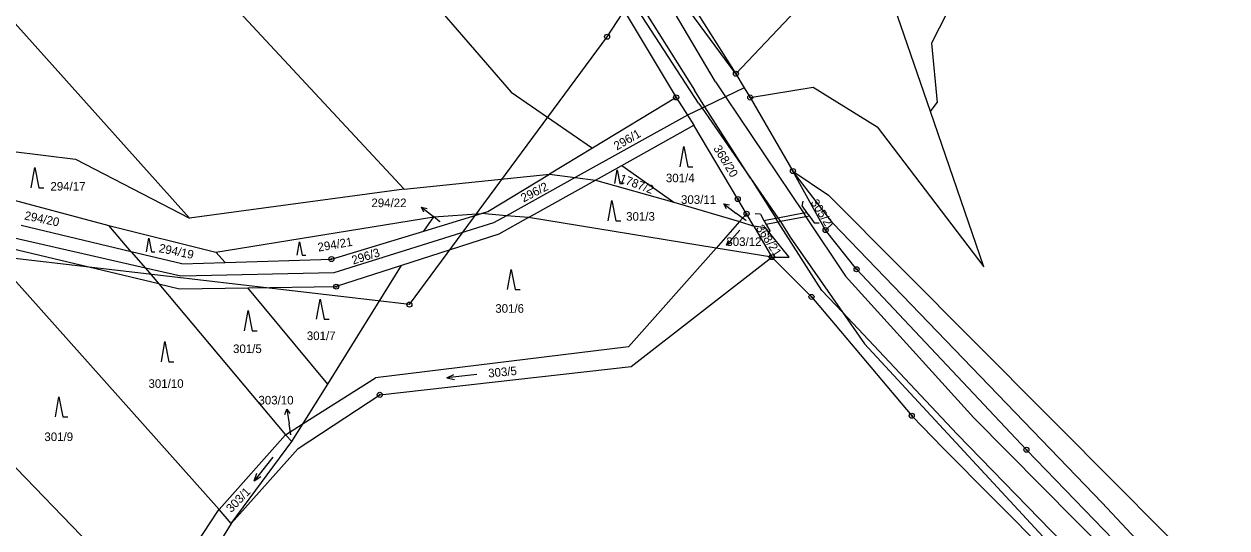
# Model space of a CAD drawing. Extents: x -762263 to -760336, y -1154405 to -1152076.
# Drawn here: x -761124.8 to -760886.7, y -1153787.3 to -1153687.5 of the extents above; entities that cross this region are included whole.
import ezdxf

# ---------------------------------------------------------------- set-up
doc = ezdxf.new("R2010")
doc.units = 0
for name, color, linetype in [('Vrstva 1', 7, 'Continuous'), ('Vrstva 10', 7, 'Continuous'), ('Vrstva 12', 7, 'Continuous'), ('Vrstva 13', 7, 'Continuous'), ('Vrstva 16', 7, 'Continuous'), ('Vrstva 18', 7, 'Continuous'), ('Vrstva 24', 7, 'Continuous'), ('Vrstva 25', 7, 'Continuous'), ('Vrstva 26', 7, 'Continuous'), ('Vrstva 4', 7, 'Continuous'), ('Vrstva 6', 7, 'Continuous')]:
    doc.layers.add(name, color=color, linetype=linetype)

msp = doc.modelspace()

# ---------------------------------------------------------------- linework, layer by layer
at = {"layer": 'Vrstva 1'}
for p, q in [((-760991.27, -1153703.15), (-761052.6, -1153608.54)), ((-760928.42, -1153658.17), (-760945.15, -1153691.28)), ((-760983.9, -1153697.32), (-760959.99, -1153671.97)), ((-760983.9, -1153697.32), (-761000.86, -1153674.38)), ((-761008.97, -1153679.88), (-760995.71, -1153702.01)), ((-760945.38, -1153704.81), (-760953.71, -1153680.58)), ((-760991.4, -1153685.47), (-760983.9, -1153697.32)), ((-760945.15, -1153691.28), (-760944.07, -1153703.02)), ((-760983.9, -1153697.32), (-760982.23, -1153700.09)), ((-760982.23, -1153700.09), (-760981.06, -1153702.03)), ((-760981.06, -1153702.03), (-760968.63, -1153699.98)), ((-760968.63, -1153699.98), (-760955.91, -1153707.82)), ((-760995.71, -1153702.01), (-761012.25, -1153712.06)), ((-760995.71, -1153702.01), (-760993.47, -1153705.56)), ((-760981.06, -1153702.03), (-760972.6, -1153716.6)), ((-760945.38, -1153704.81), (-760944.07, -1153703.02)), ((-760991.27, -1153703.15), (-760990.58, -1153704.16)), ((-760990.58, -1153704.16), (-760981.02, -1153718.01)), ((-760934.8, -1153735.55), (-760945.38, -1153704.81)), ((-761006.49, -1153715.49), (-760992.23, -1153707.52)), ((-760993.47, -1153705.56), (-760992.23, -1153707.52)), ((-760983.52, -1153722.14), (-760992.23, -1153707.52)), ((-760955.91, -1153707.82), (-760934.8, -1153735.55)), ((-761012.25, -1153712.06), (-761020.81, -1153717.25)), ((-761032.98, -1153724.64), (-761020.81, -1153717.25)), ((-761020.81, -1153717.25), (-761015.68, -1153717.89)), ((-761011.67, -1153718.39), (-761006.49, -1153715.49)), ((-760966.13, -1153728.28), (-760972.6, -1153716.6)), ((-760964.72, -1153726.91), (-760972.6, -1153716.6)), ((-760972.6, -1153716.6), (-760965.58, -1153721.41)), ((-761024.92, -1153725.81), (-761011.67, -1153718.39)), ((-761015.68, -1153717.89), (-761011.67, -1153718.39)), ((-760981.02, -1153718.01), (-760975.59, -1153725.89)), ((-760981.78, -1153725.05), (-760983.52, -1153722.14)), ((-760907.58, -1153779.67), (-760965.58, -1153721.41)), ((-761045.64, -1153728.48), (-761034.25, -1153725.02)), ((-761034.25, -1153725.02), (-761032.98, -1153724.64)), ((-761029.28, -1153725.44), (-761034.25, -1153725.02)), ((-761024.92, -1153725.81), (-761030.81, -1153729.1)), ((-761024.92, -1153725.81), (-761029.28, -1153725.44)), ((-760983.17, -1153726.62), (-760987.8, -1153731.85)), ((-760981.78, -1153725.05), (-760983.17, -1153726.62)), ((-760980.35, -1153727.51), (-760981.78, -1153725.05)), ((-760975.59, -1153725.89), (-760975.09, -1153726.62)), ((-760975.09, -1153726.62), (-760973.17, -1153729.68)), ((-760966.13, -1153728.28), (-760964.72, -1153726.91)), ((-760964.72, -1153726.91), (-760911.39, -1153782.31)), ((-761103.58, -1153732.57), (-761125.37, -1153727.38)), ((-761063.95, -1153734.04), (-761045.64, -1153728.48)), ((-761030.81, -1153729.1), (-761050.11, -1153735.34)), ((-760978.04, -1153727.86), (-760980.35, -1153727.51)), ((-760980.35, -1153727.51), (-760976.8, -1153733.64)), ((-760973.38, -1153733.63), (-760978.04, -1153727.86)), ((-760959.99, -1153736.06), (-760966.13, -1153728.28)), ((-760973.17, -1153729.68), (-760962.77, -1153744.57)), ((-761098.09, -1153738.93), (-761127.23, -1153731.99)), ((-761093.57, -1153734.96), (-761103.58, -1153732.57)), ((-761103.58, -1153732.57), (-761100.75, -1153735.85)), ((-761084.95, -1153734.69), (-761063.95, -1153734.04)), ((-760987.8, -1153731.85), (-761005.12, -1153751.4)), ((-760976.8, -1153733.64), (-760973.38, -1153733.63)), ((-761100.75, -1153735.85), (-761098.09, -1153738.93)), ((-761093.57, -1153734.96), (-761084.95, -1153734.69)), ((-761050.11, -1153735.34), (-761062.98, -1153739.5)), ((-760926.38, -1153771.8), (-760959.99, -1153736.06)), ((-761098.09, -1153738.93), (-761093.99, -1153739.91)), ((-761093.99, -1153739.91), (-761080.49, -1153739.73)), ((-761080.49, -1153739.73), (-761062.98, -1153739.5)), ((-760962.77, -1153744.57), (-760958.41, -1153750.81)), ((-761005.12, -1153751.4), (-761055.22, -1153757.55)), ((-760899.41, -1153814.59), (-760958.41, -1153750.81)), ((-761069.57, -1153766.63), (-761055.22, -1153757.55)), ((-761073.03, -1153768.82), (-761069.57, -1153766.63)), ((-761086.16, -1153783.65), (-761073.03, -1153768.82)), ((-760926.38, -1153771.8), (-760907.22, -1153791.59)), ((-760907.58, -1153779.67), (-760886.7, -1153800.7)), ((-761099.25, -1153803.44), (-761086.46, -1153783.99)), ((-761086.46, -1153783.99), (-761086.16, -1153783.65)), ((-760911.39, -1153782.31), (-760891.66, -1153803.33))]:
    msp.add_line(p, q, dxfattribs=at)
at = {"layer": 'Vrstva 10'}
for p, q in [((-760982.23, -1153700.09), (-760985.94, -1153701.89)), ((-760985.94, -1153701.89), (-760990.01, -1153703.87)), ((-760990.58, -1153704.16), (-760993.47, -1153705.56)), ((-760990.01, -1153703.87), (-760990.58, -1153704.16)), ((-760993.47, -1153705.56), (-761015.68, -1153717.89)), ((-761015.68, -1153717.89), (-761029.28, -1153725.44)), ((-761031.89, -1153726.89), (-761063.47, -1153736.75)), ((-761029.28, -1153725.44), (-761031.89, -1153726.89)), ((-761100.75, -1153735.85), (-761126.41, -1153729.97)), ((-761093.78, -1153737.45), (-761100.75, -1153735.85)), ((-761063.47, -1153736.75), (-761093.78, -1153737.45))]:
    msp.add_line(p, q, dxfattribs=at)
at = {"layer": 'Vrstva 12'}
for p, q in [((-761009.38, -1153690), (-760994.3, -1153666.9)), ((-761048.52, -1153743.06), (-761009.38, -1153690)), ((-761048.52, -1153743.06), (-761141.28, -1153732.19))]:
    msp.add_line(p, q, dxfattribs=at)
at = {"layer": 'Vrstva 13'}
for p, q in [((-761004.61, -1153755.29), (-760976.8, -1153733.64)), ((-760976.8, -1153733.64), (-760968.93, -1153741.52)), ((-760968.93, -1153741.52), (-760964.27, -1153747.04)), ((-760964.27, -1153747.04), (-760949.08, -1153765.07)), ((-761054.38, -1153760.92), (-761004.61, -1153755.29)), ((-761070.52, -1153771.55), (-761054.38, -1153760.92)), ((-760949.08, -1153765.07), (-760942.84, -1153771.46)), ((-761083.77, -1153786.39), (-761070.52, -1153771.55)), ((-760942.84, -1153771.46), (-760932.94, -1153781.45)), ((-760932.94, -1153781.45), (-760916.7, -1153797.84)), ((-761083.77, -1153786.39), (-761096.39, -1153806.55))]:
    msp.add_line(p, q, dxfattribs=at)
at = {"layer": 'Vrstva 16'}
for p, q in [((-761046.109, -1153723.751), (-761043.77, -1153725.63)), ((-760986.274, -1153723.102), (-760983.88, -1153724.91)), ((-761042.49, -1153726.66), (-761043.77, -1153725.63)), ((-760981.9, -1153726.4), (-760983.88, -1153724.91)), ((-761072.797, -1153763.735), (-761072.34, -1153766.7)), ((-761072.01, -1153768.85), (-761072.34, -1153766.7))]:
    msp.add_line(p, q, dxfattribs=at)
for points in [[(-761045.642, -1153724.767), (-761046.109, -1153723.751), (-761045.016, -1153723.988)], [(-760985.777, -1153724.104), (-760986.274, -1153723.102), (-760985.175, -1153723.306)], [(-761073.139, -1153764.8), (-761072.797, -1153763.735), (-761072.151, -1153764.647)]]:
    msp.add_lwpolyline(points, dxfattribs=at)
at = {"layer": 'Vrstva 24'}
for centre, radius in [((-760983.9, -1153697.32), 0.5), ((-760983.9, -1153697.32), 0.1), ((-760995.71, -1153702.01), 0.5), ((-760995.71, -1153702.01), 0.1), ((-760981.06, -1153702.03), 0.5), ((-760981.06, -1153702.03), 0.1), ((-760972.6, -1153716.6), 0.5), ((-760972.6, -1153716.6), 0.1), ((-760983.52, -1153722.14), 0.5), ((-760983.52, -1153722.14), 0.1), ((-760981.78, -1153725.05), 0.5), ((-760981.78, -1153725.05), 0.1), ((-760966.13, -1153728.28), 0.5), ((-760966.13, -1153728.28), 0.1), ((-761063.95, -1153734.04), 0.5), ((-761063.95, -1153734.04), 0.1), ((-760976.8, -1153733.64), 0.5), ((-760976.8, -1153733.64), 0.1), ((-760959.99, -1153736.06), 0.5), ((-760959.99, -1153736.06), 0.1), ((-761062.98, -1153739.5), 0.5), ((-761062.98, -1153739.5), 0.1), ((-760968.93, -1153741.52), 0.5), ((-760968.93, -1153741.52), 0.1), ((-761054.38, -1153760.92), 0.5), ((-761054.38, -1153760.92), 0.1), ((-760949.08, -1153765.07), 0.5), ((-760949.08, -1153765.07), 0.1), ((-760926.38, -1153771.8), 0.5), ((-760926.38, -1153771.8), 0.1)]:
    msp.add_circle(centre, radius, dxfattribs=at)
at = {"layer": 'Vrstva 25'}
for points in [[(-760994.91, -1153715.76), (-760994.21, -1153711.76), (-760993.41, -1153715.76), (-760992.41, -1153715.76)], [(-761123.38, -1153719.93), (-761122.68, -1153715.93), (-761121.88, -1153719.93), (-761120.88, -1153719.93)], [(-761007.859, -1153719.06), (-761007.39, -1153716.38), (-761006.854, -1153719.06), (-761006.184, -1153719.06)], [(-761009.17, -1153726.44), (-761008.47, -1153722.44), (-761007.67, -1153726.44), (-761006.67, -1153726.44)], [(-760983.084, -1153728.279), (-760985.756, -1153731.281), (-760984.838, -1153730.753)], [(-761100.559, -1153732.6), (-761100.09, -1153729.92), (-761099.554, -1153732.6), (-761098.884, -1153732.6)], [(-761070.719, -1153733.28), (-761070.25, -1153730.6), (-761069.714, -1153733.28), (-761069.044, -1153733.28)], [(-760985.756, -1153731.281), (-760985.338, -1153730.308)], [(-761029.1, -1153740.07), (-761028.4, -1153736.07), (-761027.6, -1153740.07), (-761026.6, -1153740.07)], [(-761066.88, -1153745.96), (-761066.18, -1153741.96), (-761065.38, -1153745.96), (-761064.38, -1153745.96)], [(-761081.13, -1153748.23), (-761080.43, -1153744.23), (-761079.63, -1153748.23), (-761078.63, -1153748.23)], [(-761097.61, -1153754.38), (-761096.91, -1153750.38), (-761096.11, -1153754.38), (-761095.11, -1153754.38)], [(-761035.169, -1153756.873), (-761041.131, -1153757.547), (-761039.584, -1153757.875)], [(-761041.131, -1153757.547), (-761039.697, -1153756.881)], [(-761118.59, -1153765.3), (-761117.89, -1153761.3), (-761117.09, -1153765.3), (-761116.09, -1153765.3)], [(-761075.548, -1153773.24), (-761079.252, -1153777.96), (-761077.933, -1153777.089)], [(-761079.252, -1153777.96), (-761078.719, -1153776.471)]]:
    msp.add_lwpolyline(points, dxfattribs=at)
at = {"layer": 'Vrstva 26'}
for p, q in [((-760970.79, -1153723.53), (-760970.547, -1153722.56)), ((-760979.05, -1153725.16), (-760980.046, -1153725.069)), ((-760968.41, -1153726.84), (-760967.41, -1153726.856)), ((-760977.19, -1153728.47), (-760977.578, -1153729.392))]:
    msp.add_line(p, q, dxfattribs=at)
for centre in [(-761009.38, -1153690), (-761048.52, -1153743.06)]:
    msp.add_circle(centre, 0.5, dxfattribs=at)
at = {"layer": 'Vrstva 4'}
for p, q in [((-760987.93, -1153698.92), (-761001.92, -1153675.11)), ((-761006.25, -1153678.03), (-760992.1, -1153700.58)), ((-760990.01, -1153703.87), (-760992.1, -1153700.58)), ((-760987.93, -1153698.92), (-760985.94, -1153701.89)), ((-760985.94, -1153701.89), (-760970.53, -1153724.9)), ((-760981.02, -1153718.01), (-760990.01, -1153703.87)), ((-760981.02, -1153718.01), (-760975.97, -1153725.96)), ((-760970.79, -1153723.53), (-760969.89, -1153724.78)), ((-760979.05, -1153725.16), (-760978.34, -1153726.42)), ((-760978.34, -1153726.42), (-760975.97, -1153725.96)), ((-760978.34, -1153726.42), (-760977.92, -1153727.16)), ((-760975.5, -1153726.7), (-760977.92, -1153727.16)), ((-760975.97, -1153725.96), (-760975.59, -1153725.89)), ((-760975.5, -1153726.7), (-760975.97, -1153725.96)), ((-760975.59, -1153725.89), (-760970.53, -1153724.9)), ((-760975.09, -1153726.62), (-760975.5, -1153726.7)), ((-760966.88, -1153740.27), (-760975.5, -1153726.7)), ((-760970.03, -1153725.66), (-760975.09, -1153726.62)), ((-760970.53, -1153724.9), (-760969.89, -1153724.78)), ((-760970.53, -1153724.9), (-760970.03, -1153725.66)), ((-760969.35, -1153725.53), (-760970.03, -1153725.66)), ((-760970.03, -1153725.66), (-760962.17, -1153737.39)), ((-760969.89, -1153724.78), (-760969.35, -1153725.53)), ((-760969.35, -1153725.53), (-760968.41, -1153726.84)), ((-760977.92, -1153727.16), (-760977.19, -1153728.47)), ((-760936.82, -1153765.51), (-760962.17, -1153737.39)), ((-760962.77, -1153744.57), (-760966.88, -1153740.27)), ((-760940.11, -1153768.69), (-760962.77, -1153744.57)), ((-760909.48, -1153793.08), (-760936.82, -1153765.51)), ((-760913.71, -1153795.87), (-760940.11, -1153768.69))]:
    msp.add_line(p, q, dxfattribs=at)
at = {"layer": 'Vrstva 6'}
for p, q in [((-761118.57, -1153596.92), (-761028.35, -1153700.96)), ((-761150.08, -1153612.09), (-761049.56, -1153720.16)), ((-761138.14, -1153674.54), (-761092.02, -1153725.92)), ((-761028.35, -1153700.96), (-761012.25, -1153712.06)), ((-761127.38, -1153712.67), (-761114.6, -1153714.25)), ((-761114.6, -1153714.25), (-761092.02, -1153725.92)), ((-761049.56, -1153720.16), (-761020.81, -1153717.25)), ((-761006.49, -1153715.49), (-760996.18, -1153722.77)), ((-761011.67, -1153718.39), (-760996.18, -1153722.77)), ((-761129.76, -1153721.55), (-761108.04, -1153727.41)), ((-761049.56, -1153720.16), (-761092.02, -1153725.92)), ((-760996.18, -1153722.77), (-760983.17, -1153726.62)), ((-761086.86, -1153732.66), (-761043.71, -1153725.7)), ((-761045.64, -1153728.48), (-761043.71, -1153725.7)), ((-761043.71, -1153725.7), (-761034.25, -1153725.02)), ((-760987.8, -1153731.85), (-761024.92, -1153725.81)), ((-760983.17, -1153726.62), (-760980.35, -1153727.51)), ((-761103.58, -1153732.57), (-761108.04, -1153727.41)), ((-761108.04, -1153727.41), (-761086.86, -1153732.66)), ((-761086.86, -1153732.66), (-761084.95, -1153734.69)), ((-760976.8, -1153733.64), (-760987.8, -1153731.85)), ((-761086.16, -1153783.65), (-761128.45, -1153736.16)), ((-761064.63, -1153758.84), (-761050.11, -1153735.34)), ((-761098.09, -1153738.93), (-761073.03, -1153768.82)), ((-761064.63, -1153758.84), (-761080.49, -1153739.73)), ((-761069.57, -1153766.63), (-761064.63, -1153758.84)), ((-761136.8, -1153764.7), (-761099.25, -1153803.44)), ((-761071.81, -1153770.16), (-761069.57, -1153766.63)), ((-761073.03, -1153768.82), (-761071.81, -1153770.16)), ((-761083.77, -1153786.39), (-761071.81, -1153770.16)), ((-761083.77, -1153786.39), (-761086.16, -1153783.65))]:
    msp.add_line(p, q, dxfattribs=at)

# ---------------------------------------------------------------- texts
at = {"layer": 'Vrstva 16'}
for s, p in [('294/22', (-761056.035, -1153723.75)), ('303/11', (-760994.762, -1153723.1)), ('303/10', (-761078.392, -1153762.83))]:
    msp.add_text(s, height=1.7, dxfattribs=at).set_placement(p)
at = {"layer": 'Vrstva 18'}
for s, rotation, p in [('296/1', 30.08028, (-761007.455, -1153712.541)), ('368/20', 301.4331, (-760988.426, -1153712.103)), ('1787/2', 339.4202, (-761007.082, -1153718.716)), ('296/2', 27.1582, (-761025.919, -1153722.832)), ('305/2', 301.83417, (-760969.164, -1153722.824)), ('294/20', 348.24375, (-761124.816, -1153726.175)), ('368/21', 303.61034, (-760979.983, -1153727.92)), ('294/19', 348.41564, (-761098.21, -1153732.637)), ('294/21', 9.74028, (-761066.525, -1153732.563)), ('296/3', 17.18873, (-761059.643, -1153735.13)), ('303/5', 5.21392, (-761032.846, -1153757.494)), ('303/1', 45.89392, (-761083.767, -1153784.359))]:
    msp.add_text(s, height=1.7, rotation=rotation, dxfattribs=at).set_placement(p)
for s, height, p in [('301/4', 1.7, (-760997.749, -1153718.82)), ('294/17', 1.7, (-761119.568, -1153720.47)), ('294/22', 0.1, (-761042.745, -1153726.66)), ('301/3', 1.7, (-761005.616, -1153726.44)), ('303/11', 0.1, (-760982.113, -1153726.4)), ('303/12', 1.7, (-760985.779, -1153731.44)), ('301/6', 1.7, (-761031.519, -1153744.67)), ('301/7', 1.7, (-761068.819, -1153750.08)), ('301/5', 1.7, (-761083.426, -1153752.65)), ('301/10', 1.7, (-761100.157, -1153759.54)), ('301/9', 1.7, (-761120.769, -1153770.08)), ('303/10', 0.1, (-761072.245, -1153768.85))]:
    msp.add_text(s, height=height, dxfattribs=at).set_placement(p)

doc.saveas('drawing.dxf')
